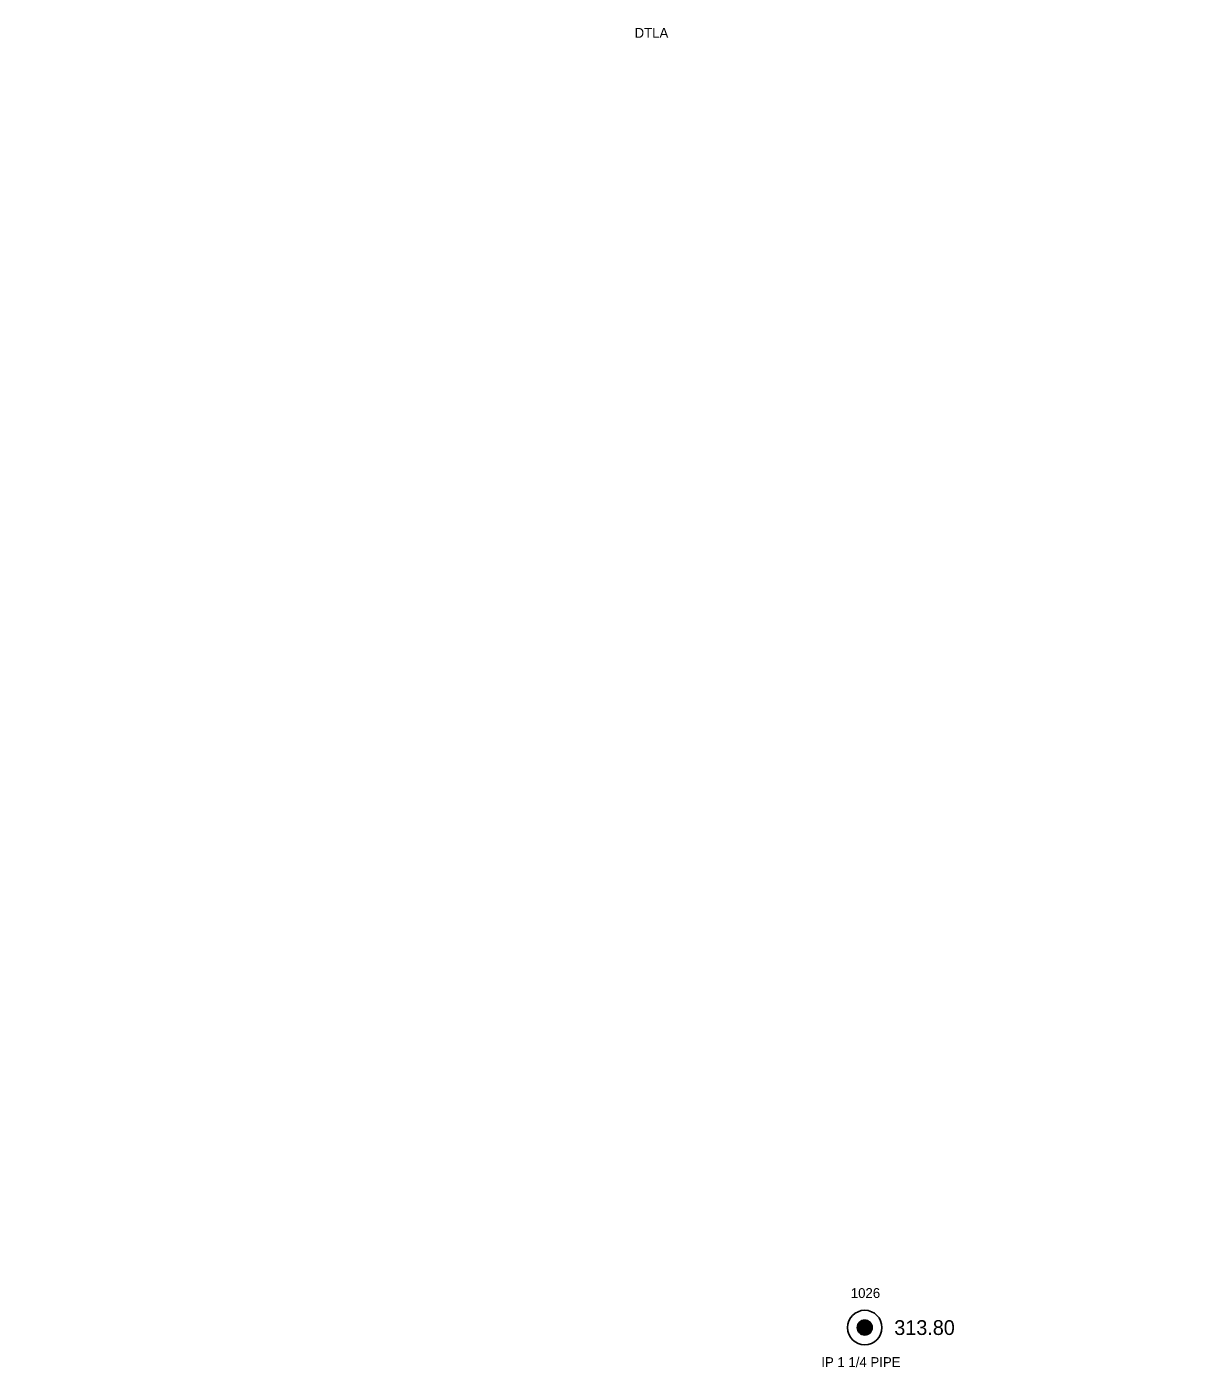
# Model space of a CAD drawing. Extents: x 1865045 to 1867370, y 910391 to 914218.
# Drawn here: x 1866502.5 to 1866620.1, y 910428 to 910563.9 of the extents above; entities that cross this region are included whole.
import ezdxf

# ---------------------------------------------------------------- set-up
doc = ezdxf.new("R2010")
doc.units = 0
for name, color, linetype in [('RD_EX_DV_Prop_txCode', 7, 'Continuous'), ('RD_EX_DV_PropPin', 7, 'Continuous'), ('RD_EX_H2O_txCode', 7, 'Continuous'), ('RD_EX_TX_DV_Prop_ELEV', 7, 'Continuous'), ('RD_HC_Cl', 7, 'Continuous'), ('RD_SMD_Locator', 7, 'Continuous')]:
    doc.layers.add(name, color=color, linetype=linetype)

msp = doc.modelspace()

# ---------------------------------------------------------------- linework, layer by layer
at = {"layer": 'RD_EX_DV_PropPin'}
for p, q in [((1866586.96, 910431.48), (1866586.96, 910432.58)), ((1866586.99, 910431.45), (1866586.99, 910432.61)), ((1866587.03, 910431.42), (1866587.03, 910432.64)), ((1866587.06, 910431.39), (1866587.06, 910432.66)), ((1866587.1, 910431.37), (1866587.1, 910432.68)), ((1866587.13, 910431.35), (1866587.13, 910432.7)), ((1866587.17, 910431.33), (1866587.17, 910432.72)), ((1866587.2, 910431.32), (1866587.2, 910432.74)), ((1866587.24, 910431.31), (1866587.24, 910432.75)), ((1866587.27, 910431.3), (1866587.27, 910432.76)), ((1866587.31, 910431.29), (1866587.31, 910432.77)), ((1866587.34, 910431.28), (1866587.34, 910432.78)), ((1866587.38, 910431.27), (1866587.38, 910432.78)), ((1866587.41, 910431.27), (1866587.41, 910432.79)), ((1866587.45, 910431.27), (1866587.45, 910432.79)), ((1866587.48, 910431.27), (1866587.48, 910432.79)), ((1866587.52, 910431.27), (1866587.52, 910432.79)), ((1866587.55, 910431.27), (1866587.55, 910432.79)), ((1866587.59, 910431.27), (1866587.59, 910432.78)), ((1866587.62, 910431.28), (1866587.62, 910432.78)), ((1866587.66, 910431.29), (1866587.66, 910432.77)), ((1866587.69, 910431.3), (1866587.69, 910432.76)), ((1866587.73, 910431.31), (1866587.73, 910432.75)), ((1866587.76, 910431.32), (1866587.76, 910432.74)), ((1866587.8, 910431.33), (1866587.8, 910432.72)), ((1866587.83, 910431.35), (1866587.83, 910432.7)), ((1866587.87, 910431.37), (1866587.87, 910432.68)), ((1866587.9, 910431.39), (1866587.9, 910432.66)), ((1866587.94, 910431.42), (1866587.94, 910432.64)), ((1866587.97, 910431.45), (1866587.97, 910432.61)), ((1866588.01, 910431.48), (1866588.01, 910432.58)), ((1866586.75, 910431.83), (1866586.75, 910432.22)), ((1866586.78, 910431.73), (1866586.78, 910432.33)), ((1866586.82, 910431.66), (1866586.82, 910432.4)), ((1866586.85, 910431.6), (1866586.85, 910432.45)), ((1866586.89, 910431.55), (1866586.89, 910432.5)), ((1866586.92, 910431.51), (1866586.92, 910432.54)), ((1866588.04, 910431.51), (1866588.04, 910432.54)), ((1866588.08, 910431.55), (1866588.08, 910432.5)), ((1866588.11, 910431.6), (1866588.11, 910432.45)), ((1866588.15, 910431.66), (1866588.15, 910432.4)), ((1866588.18, 910431.73), (1866588.18, 910432.33)), ((1866588.22, 910431.83), (1866588.22, 910432.22))]:
    msp.add_line(p, q, dxfattribs=at)
for radius in [1.75, 0.761]:
    msp.add_circle((1866587.48, 910432.03), radius, dxfattribs=at)
at = {"layer": 'RD_HC_Cl'}
msp.add_arc((1867567.42, 911345.48), 1181.58, 205.67399, 227.8297, dxfattribs=at)
at = {"layer": 'RD_SMD_Locator'}
msp.add_circle((1866587.48, 910432.03), 0.15, dxfattribs=at)

# ---------------------------------------------------------------- texts
at = {"layer": 'RD_EX_DV_Prop_txCode'}
for s, p in [('1026', (1866586.07, 910435.03)), ('IP 1 1/4 PIPE', (1866583.08, 910428.03))]:
    msp.add_text(s, height=1, dxfattribs=at).set_placement(p)
at = {"layer": 'RD_EX_H2O_txCode'}
msp.add_text('DTLA', height=1, dxfattribs=at).set_placement((1866564.14, 910562.8))
at = {"layer": 'RD_EX_TX_DV_Prop_ELEV'}
msp.add_text('313.80', height=1.5, dxfattribs=at).set_placement((1866590.48, 910431.28))

doc.saveas('drawing.dxf')
